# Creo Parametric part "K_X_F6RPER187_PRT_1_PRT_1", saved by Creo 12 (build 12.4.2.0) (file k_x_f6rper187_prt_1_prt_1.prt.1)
Units: Custom; MM, KILOGRAM, SECS

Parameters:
  PTC_WM_ITERATION = "0"
  PTC_WM_VERSION = "-.0"
  PTC_WM_LIFECYCLE_STATE = "In Work"
  PTC_WM_LIFECYCLE = "MO_CADDocument"
  PTC_WM_CREATED_BY = "Maximilian Roepper (Z0017RMS: MO)"
  PTC_WM_CREATED_ON = "18-Sep-26 11:36:42 AM"
  PTC_WM_MODIFIED_BY = "Maximilian Roepper (Z0017RMS: MO)"
  PTC_WM_MODIFIED_ON = "18-Sep-26 11:36:46 AM"
  PDMLINKNUMBER = "PDM000071454930"
  PTC_WM_NAME = "k_x_f6rper187_prt_1_prt_1.prt"
  PTC_WM_NUMBER = "PDM000071454930"

Other parameters: WEIGHT, WEIGHT_FACTOR, WEIGHT_ADD, _MASS_TEMP, _DIFF_TEMP, MC_ERRORS, SUPPLIER

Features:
  1. coordinate system
  2. datum plane "PRT_YZ"
  3. datum plane "PRT_XY"
  4. datum plane "PRT_XZ"
  5. coordinate system
  6. datum axis
  7. datum axis
  8. datum axis
  9. coordinate system
  10. imported feature
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
Other named items: PRT, SIEMENS_MO, DRW_VIEW_ORG, PRT_X, PRT_Y, PRT_Z, CS0, ROUGH_GROB

Layers: 00_STD_CSYS-KSYS, 01_STD_PLANES-EBENEN, 02_STD_AXES-ACHSEN, 03_STD_CSYS-KSYS, 24_IMPORT_FEAT-IMPORT_KE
